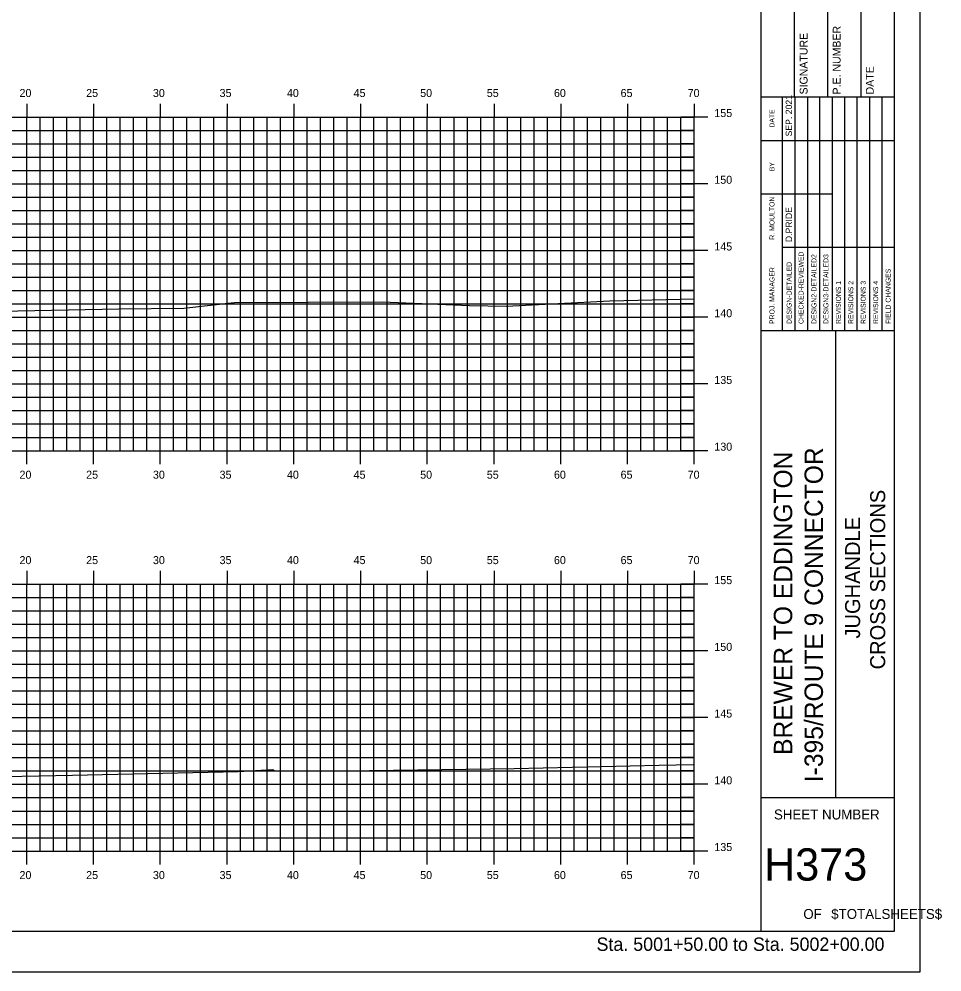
# Model space of a CAD drawing. Extents: x 851195 to 851367, y 365876 to 365986.
# Drawn here: x 851297.6 to 851366.7, y 365875.8 to 365947.2 of the extents above; entities that cross this region are included whole.
import ezdxf

# ---------------------------------------------------------------- set-up
doc = ezdxf.new("R2010")
doc.units = 0
for name, color, linetype in [('BORDER', 7, 'Continuous'), ('H_V ANNOTATION', 7, 'Continuous'), ('MAJOR', 7, 'Continuous'), ('MINOR', 7, 'Continuous'), ('PLOT BOUNDARY', 7, 'Continuous'), ('S_Roadway_Centerline', 7, 'Continuous')]:
    doc.layers.add(name, color=color, linetype=linetype)

msp = doc.modelspace()

# ---------------------------------------------------------------- linework, layer by layer
at = {"layer": 'BORDER'}
for p, q in [((851353.142, 365878.833), (851353.142, 365983.833)), ((851355.642, 365941.336), (851355.642, 365949.984)), ((851358.142, 365941.336), (851358.142, 365949.984)), ((851360.642, 365941.336), (851360.642, 365949.984)), ((851353.142, 365941.336), (851363.142, 365941.336)), ((851353.142, 365923.836), (851363.142, 365923.836)), ((851358.733, 365888.836), (851358.733, 365923.836)), ((851353.142, 365888.836), (851363.142, 365888.836))]:
    msp.add_line(p, q, dxfattribs=at)
msp.add_lwpolyline([(851203.142, 365878.833), (851363.142, 365878.833), (851363.142, 365983.833), (851203.142, 365983.833)], close=True, dxfattribs=at)
for points in [[(851354.757, 365938.086), (851354.757, 365941.336)], [(851355.69, 365923.839), (851355.69, 365941.336)], [(851356.621, 365941.336), (851356.621, 365923.839)], [(851357.553, 365923.839), (851357.553, 365941.336)], [(851358.485, 365923.839), (851358.485, 365941.336)], [(851359.416, 365923.839), (851359.416, 365941.336)], [(851360.348, 365923.839), (851360.348, 365941.336)], [(851361.28, 365923.839), (851361.28, 365941.336)], [(851362.211, 365923.839), (851362.211, 365941.336)], [(851354.758, 365923.839), (851354.758, 365940.63)], [(851353.142, 365938.086), (851363.142, 365938.086)], [(851353.142, 365934.086), (851354.758, 365934.086)], [(851354.757, 365934.086), (851358.484, 365934.086)], [(851354.757, 365930.086), (851363.142, 365930.086)]]:
    msp.add_lwpolyline(points, dxfattribs=at)
at = {"layer": 'MAJOR'}
for p, q in [((851298.142, 365940.835), (851298.142, 365939.833)), ((851303.142, 365940.835), (851303.142, 365939.833)), ((851308.142, 365940.835), (851308.142, 365939.833)), ((851313.142, 365940.835), (851313.142, 365939.833)), ((851318.142, 365940.835), (851318.142, 365939.833)), ((851323.142, 365940.835), (851323.142, 365939.833)), ((851328.142, 365940.835), (851328.142, 365939.833)), ((851333.142, 365940.835), (851333.142, 365939.833)), ((851338.142, 365940.835), (851338.142, 365939.833)), ((851343.142, 365940.835), (851343.142, 365939.833)), ((851348.142, 365940.835), (851348.142, 365939.833)), ((851208.142, 365939.833), (851348.142, 365939.833)), ((851208.142, 365939.833), (851348.142, 365939.833)), ((851298.142, 365914.833), (851298.142, 365939.833)), ((851303.142, 365914.833), (851303.142, 365939.833)), ((851308.142, 365914.833), (851308.142, 365939.833)), ((851313.142, 365914.833), (851313.142, 365939.833)), ((851318.142, 365914.833), (851318.142, 365939.833)), ((851323.142, 365914.833), (851323.142, 365939.833)), ((851328.142, 365914.833), (851328.142, 365939.833)), ((851333.142, 365914.833), (851333.142, 365939.833)), ((851338.142, 365914.833), (851338.142, 365939.833)), ((851343.142, 365914.833), (851343.142, 365939.833)), ((851349.144, 365939.833), (851347.14, 365939.833)), ((851348.142, 365914.833), (851348.142, 365939.833)), ((851348.142, 365914.833), (851348.142, 365939.833)), ((851208.142, 365934.833), (851348.142, 365934.833)), ((851349.144, 365934.833), (851347.14, 365934.833)), ((851208.142, 365929.833), (851348.142, 365929.833)), ((851349.144, 365929.833), (851347.14, 365929.833)), ((851208.142, 365924.833), (851348.142, 365924.833)), ((851349.144, 365924.833), (851347.14, 365924.833)), ((851208.142, 365919.833), (851348.142, 365919.833)), ((851349.144, 365919.833), (851347.14, 365919.833)), ((851208.142, 365914.833), (851348.142, 365914.833)), ((851208.142, 365914.833), (851348.142, 365914.833)), ((851298.142, 365913.831), (851298.142, 365914.833)), ((851303.142, 365913.831), (851303.142, 365914.833)), ((851308.142, 365913.831), (851308.142, 365914.833)), ((851313.142, 365913.831), (851313.142, 365914.833)), ((851318.142, 365913.831), (851318.142, 365914.833)), ((851323.142, 365913.831), (851323.142, 365914.833)), ((851328.142, 365913.831), (851328.142, 365914.833)), ((851333.142, 365913.831), (851333.142, 365914.833)), ((851338.142, 365913.831), (851338.142, 365914.833)), ((851343.142, 365913.831), (851343.142, 365914.833)), ((851349.144, 365914.833), (851347.14, 365914.833)), ((851348.142, 365913.831), (851348.142, 365914.833)), ((851298.142, 365905.835), (851298.142, 365904.833)), ((851303.142, 365905.835), (851303.142, 365904.833)), ((851308.142, 365905.835), (851308.142, 365904.833)), ((851313.142, 365905.835), (851313.142, 365904.833)), ((851318.142, 365905.835), (851318.142, 365904.833)), ((851323.142, 365905.835), (851323.142, 365904.833)), ((851328.142, 365905.835), (851328.142, 365904.833)), ((851333.142, 365905.835), (851333.142, 365904.833)), ((851338.142, 365905.835), (851338.142, 365904.833)), ((851343.142, 365905.835), (851343.142, 365904.833)), ((851348.142, 365905.835), (851348.142, 365904.833)), ((851208.142, 365904.833), (851348.142, 365904.833)), ((851208.142, 365904.833), (851348.142, 365904.833)), ((851298.142, 365884.833), (851298.142, 365904.833)), ((851303.142, 365884.833), (851303.142, 365904.833)), ((851308.142, 365884.833), (851308.142, 365904.833)), ((851313.142, 365884.833), (851313.142, 365904.833)), ((851318.142, 365884.833), (851318.142, 365904.833)), ((851323.142, 365884.833), (851323.142, 365904.833)), ((851328.142, 365884.833), (851328.142, 365904.833)), ((851333.142, 365884.833), (851333.142, 365904.833)), ((851338.142, 365884.833), (851338.142, 365904.833)), ((851343.142, 365884.833), (851343.142, 365904.833)), ((851349.144, 365904.833), (851347.14, 365904.833)), ((851348.142, 365884.833), (851348.142, 365904.833)), ((851348.142, 365884.833), (851348.142, 365904.833)), ((851208.142, 365899.833), (851348.142, 365899.833)), ((851349.144, 365899.833), (851347.14, 365899.833)), ((851208.142, 365894.833), (851348.142, 365894.833)), ((851349.144, 365894.833), (851347.14, 365894.833)), ((851208.142, 365889.833), (851348.142, 365889.833)), ((851349.144, 365889.833), (851347.14, 365889.833)), ((851208.142, 365884.833), (851348.142, 365884.833)), ((851208.142, 365884.833), (851348.142, 365884.833)), ((851298.142, 365883.831), (851298.142, 365884.833)), ((851303.142, 365883.831), (851303.142, 365884.833)), ((851308.142, 365883.831), (851308.142, 365884.833)), ((851313.142, 365883.831), (851313.142, 365884.833)), ((851318.142, 365883.831), (851318.142, 365884.833)), ((851323.142, 365883.831), (851323.142, 365884.833)), ((851328.142, 365883.831), (851328.142, 365884.833)), ((851333.142, 365883.831), (851333.142, 365884.833)), ((851338.142, 365883.831), (851338.142, 365884.833)), ((851343.142, 365883.831), (851343.142, 365884.833)), ((851349.144, 365884.833), (851347.14, 365884.833)), ((851348.142, 365883.831), (851348.142, 365884.833))]:
    msp.add_line(p, q, dxfattribs=at)
at = {"layer": 'MINOR'}
for p, q in [((851299.142, 365914.833), (851299.142, 365939.833)), ((851300.142, 365914.833), (851300.142, 365939.833)), ((851301.142, 365914.833), (851301.142, 365939.833)), ((851302.142, 365914.833), (851302.142, 365939.833)), ((851304.142, 365914.833), (851304.142, 365939.833)), ((851305.142, 365914.833), (851305.142, 365939.833)), ((851306.142, 365914.833), (851306.142, 365939.833)), ((851307.142, 365914.833), (851307.142, 365939.833)), ((851309.142, 365914.833), (851309.142, 365939.833)), ((851310.142, 365914.833), (851310.142, 365939.833)), ((851311.142, 365914.833), (851311.142, 365939.833)), ((851312.142, 365914.833), (851312.142, 365939.833)), ((851314.142, 365914.833), (851314.142, 365939.833)), ((851315.142, 365914.833), (851315.142, 365939.833)), ((851316.142, 365914.833), (851316.142, 365939.833)), ((851317.142, 365914.833), (851317.142, 365939.833)), ((851319.142, 365914.833), (851319.142, 365939.833)), ((851320.142, 365914.833), (851320.142, 365939.833)), ((851321.142, 365914.833), (851321.142, 365939.833)), ((851322.142, 365914.833), (851322.142, 365939.833)), ((851324.142, 365914.833), (851324.142, 365939.833)), ((851325.142, 365914.833), (851325.142, 365939.833)), ((851326.142, 365914.833), (851326.142, 365939.833)), ((851327.142, 365914.833), (851327.142, 365939.833)), ((851329.142, 365914.833), (851329.142, 365939.833)), ((851330.142, 365914.833), (851330.142, 365939.833)), ((851331.142, 365914.833), (851331.142, 365939.833)), ((851332.142, 365914.833), (851332.142, 365939.833)), ((851334.142, 365914.833), (851334.142, 365939.833)), ((851335.142, 365914.833), (851335.142, 365939.833)), ((851336.142, 365914.833), (851336.142, 365939.833)), ((851337.142, 365914.833), (851337.142, 365939.833)), ((851339.142, 365914.833), (851339.142, 365939.833)), ((851340.142, 365914.833), (851340.142, 365939.833)), ((851341.142, 365914.833), (851341.142, 365939.833)), ((851342.142, 365914.833), (851342.142, 365939.833)), ((851344.142, 365914.833), (851344.142, 365939.833)), ((851345.142, 365914.833), (851345.142, 365939.833)), ((851346.142, 365914.833), (851346.142, 365939.833)), ((851347.142, 365914.833), (851347.142, 365939.833)), ((851208.142, 365938.833), (851348.142, 365938.833)), ((851348.142, 365938.833), (851347.14, 365938.833)), ((851208.142, 365937.833), (851348.142, 365937.833)), ((851348.142, 365937.833), (851347.14, 365937.833)), ((851208.142, 365936.833), (851348.142, 365936.833)), ((851348.142, 365936.833), (851347.14, 365936.833)), ((851208.142, 365935.833), (851348.142, 365935.833)), ((851348.142, 365935.833), (851347.14, 365935.833)), ((851208.142, 365933.833), (851348.142, 365933.833)), ((851348.142, 365933.833), (851347.14, 365933.833)), ((851208.142, 365932.833), (851348.142, 365932.833)), ((851348.142, 365932.833), (851347.14, 365932.833)), ((851208.142, 365931.833), (851348.142, 365931.833)), ((851348.142, 365931.833), (851347.14, 365931.833)), ((851208.142, 365930.833), (851348.142, 365930.833)), ((851348.142, 365930.833), (851347.14, 365930.833)), ((851208.142, 365928.833), (851348.142, 365928.833)), ((851348.142, 365928.833), (851347.14, 365928.833)), ((851208.142, 365927.833), (851348.142, 365927.833)), ((851348.142, 365927.833), (851347.14, 365927.833)), ((851208.142, 365926.833), (851348.142, 365926.833)), ((851348.142, 365926.833), (851347.14, 365926.833)), ((851208.142, 365925.833), (851348.142, 365925.833)), ((851348.142, 365925.833), (851347.14, 365925.833)), ((851208.142, 365923.833), (851348.142, 365923.833)), ((851348.142, 365923.833), (851347.14, 365923.833)), ((851208.142, 365922.833), (851348.142, 365922.833)), ((851348.142, 365922.833), (851347.14, 365922.833)), ((851208.142, 365921.833), (851348.142, 365921.833)), ((851348.142, 365921.833), (851347.14, 365921.833)), ((851208.142, 365920.833), (851348.142, 365920.833)), ((851348.142, 365920.833), (851347.14, 365920.833)), ((851208.142, 365918.833), (851348.142, 365918.833)), ((851348.142, 365918.833), (851347.14, 365918.833)), ((851208.142, 365917.833), (851348.142, 365917.833)), ((851348.142, 365917.833), (851347.14, 365917.833)), ((851208.142, 365916.833), (851348.142, 365916.833)), ((851348.142, 365916.833), (851347.14, 365916.833)), ((851208.142, 365915.833), (851348.142, 365915.833)), ((851348.142, 365915.833), (851347.14, 365915.833)), ((851299.142, 365884.833), (851299.142, 365904.833)), ((851300.142, 365884.833), (851300.142, 365904.833)), ((851301.142, 365884.833), (851301.142, 365904.833)), ((851302.142, 365884.833), (851302.142, 365904.833)), ((851304.142, 365884.833), (851304.142, 365904.833)), ((851305.142, 365884.833), (851305.142, 365904.833)), ((851306.142, 365884.833), (851306.142, 365904.833)), ((851307.142, 365884.833), (851307.142, 365904.833)), ((851309.142, 365884.833), (851309.142, 365904.833)), ((851310.142, 365884.833), (851310.142, 365904.833)), ((851311.142, 365884.833), (851311.142, 365904.833)), ((851312.142, 365884.833), (851312.142, 365904.833)), ((851314.142, 365884.833), (851314.142, 365904.833)), ((851315.142, 365884.833), (851315.142, 365904.833)), ((851316.142, 365884.833), (851316.142, 365904.833)), ((851317.142, 365884.833), (851317.142, 365904.833)), ((851319.142, 365884.833), (851319.142, 365904.833)), ((851320.142, 365884.833), (851320.142, 365904.833)), ((851321.142, 365884.833), (851321.142, 365904.833)), ((851322.142, 365884.833), (851322.142, 365904.833)), ((851324.142, 365884.833), (851324.142, 365904.833)), ((851325.142, 365884.833), (851325.142, 365904.833)), ((851326.142, 365884.833), (851326.142, 365904.833)), ((851327.142, 365884.833), (851327.142, 365904.833)), ((851329.142, 365884.833), (851329.142, 365904.833)), ((851330.142, 365884.833), (851330.142, 365904.833)), ((851331.142, 365884.833), (851331.142, 365904.833)), ((851332.142, 365884.833), (851332.142, 365904.833)), ((851334.142, 365884.833), (851334.142, 365904.833)), ((851335.142, 365884.833), (851335.142, 365904.833)), ((851336.142, 365884.833), (851336.142, 365904.833)), ((851337.142, 365884.833), (851337.142, 365904.833)), ((851339.142, 365884.833), (851339.142, 365904.833)), ((851340.142, 365884.833), (851340.142, 365904.833)), ((851341.142, 365884.833), (851341.142, 365904.833)), ((851342.142, 365884.833), (851342.142, 365904.833)), ((851344.142, 365884.833), (851344.142, 365904.833)), ((851345.142, 365884.833), (851345.142, 365904.833)), ((851346.142, 365884.833), (851346.142, 365904.833)), ((851347.142, 365884.833), (851347.142, 365904.833)), ((851208.142, 365903.833), (851348.142, 365903.833)), ((851348.142, 365903.833), (851347.14, 365903.833)), ((851208.142, 365902.833), (851348.142, 365902.833)), ((851348.142, 365902.833), (851347.14, 365902.833)), ((851208.142, 365901.833), (851348.142, 365901.833)), ((851348.142, 365901.833), (851347.14, 365901.833)), ((851208.142, 365900.833), (851348.142, 365900.833)), ((851348.142, 365900.833), (851347.14, 365900.833)), ((851208.142, 365898.833), (851348.142, 365898.833)), ((851348.142, 365898.833), (851347.14, 365898.833)), ((851208.142, 365897.833), (851348.142, 365897.833)), ((851348.142, 365897.833), (851347.14, 365897.833)), ((851208.142, 365896.833), (851348.142, 365896.833)), ((851348.142, 365896.833), (851347.14, 365896.833)), ((851208.142, 365895.833), (851348.142, 365895.833)), ((851348.142, 365895.833), (851347.14, 365895.833)), ((851208.142, 365893.833), (851348.142, 365893.833)), ((851348.142, 365893.833), (851347.14, 365893.833)), ((851208.142, 365892.833), (851348.142, 365892.833)), ((851348.142, 365892.833), (851347.14, 365892.833)), ((851208.142, 365891.833), (851348.142, 365891.833)), ((851348.142, 365891.833), (851347.14, 365891.833)), ((851208.142, 365890.833), (851348.142, 365890.833)), ((851348.142, 365890.833), (851347.14, 365890.833)), ((851208.142, 365888.833), (851348.142, 365888.833)), ((851348.142, 365888.833), (851347.14, 365888.833)), ((851208.142, 365887.833), (851348.142, 365887.833)), ((851348.142, 365887.833), (851347.14, 365887.833)), ((851208.142, 365886.833), (851348.142, 365886.833)), ((851348.142, 365886.833), (851347.14, 365886.833)), ((851208.142, 365885.833), (851348.142, 365885.833)), ((851348.142, 365885.833), (851347.14, 365885.833))]:
    msp.add_line(p, q, dxfattribs=at)
at = {"layer": 'PLOT BOUNDARY'}
msp.add_lwpolyline([(851195.049, 365875.774), (851365.049, 365875.774), (851365.049, 365985.774), (851195.049, 365985.774)], close=True, dxfattribs=at)
at = {"layer": 'S_Roadway_Centerline'}
for points in [[(851296.222, 365925.276), (851305.027, 365925.458), (851309.904, 365925.514), (851313.671, 365925.94), (851324.759, 365925.988), (851331.302, 365925.709), (851334.072, 365925.654), (851341.804, 365926.069), (851348.142, 365926.208)], [(851296.52, 365890.412), (851301.569, 365890.522), (851313.974, 365890.799), (851316.583, 365890.933), (851316.695, 365890.853), (851320.183, 365890.818), (851334.654, 365891.025), (851345.501, 365891.264), (851348.063, 365891.312), (851348.142, 365891.321)]]:
    msp.add_lwpolyline(points, dxfattribs=at)

# ---------------------------------------------------------------- texts
at = {"layer": 'BORDER'}
for s, height, p in [('SIGNATURE', 0.5906, (851356.623, 365941.528)), ('P.E. NUMBER', 0.59055, (851359.103, 365941.528)), ('DATE', 0.5906, (851361.583, 365941.528)), ('SEP. 2021', 0.4845, (851355.465, 365938.382)), ('DATE', 0.3714, (851354.146, 365939.042)), ('BY', 0.3714, (851354.146, 365935.771)), ('R. MOULTON', 0.3727, (851354.146, 365930.639)), ('D.PRIDE', 0.4845, (851355.465, 365930.459)), ('CHECKED-REVIEWED', 0.37275, (851356.323, 365924.324)), ('DESIGN2-DETAILED2', 0.37275, (851357.292, 365924.324)), ('DESIGN3-DETAILED3', 0.37275, (851358.186, 365924.324)), ('PROJ. MANAGER', 0.37275, (851354.146, 365924.324)), ('DESIGN-DETAILED', 0.37275, (851355.429, 365924.324)), ('FIELD CHANGES', 0.37275, (851362.845, 365924.324)), ('REVISIONS 1', 0.37275, (851359.118, 365924.324)), ('REVISIONS 2', 0.37275, (851360.05, 365924.324)), ('REVISIONS 3', 0.37275, (851360.981, 365924.324)), ('REVISIONS 4', 0.37275, (851361.913, 365924.324)), ('I-395/ROUTE 9 CONNECTOR', 1.37787, (851357.777, 365889.998)), ('BREWER TO EDDINGTON', 1.37787, (851355.476, 365892.038)), ('CROSS SECTIONS', 1.125, (851362.439, 365898.444)), ('JUGHANDLE', 1.125, (851360.561, 365900.756))]:
    msp.add_text(s, height=height, rotation=90, dxfattribs=at).set_placement(p)
for s, height, p in [('SHEET NUMBER', 0.74527, (851354.108, 365887.2)), ('H373', 2.4194, (851353.362, 365882.616)), ('OF', 0.7453, (851356.309, 365879.746)), ('$TOTALSHEETS$', 0.74527, (851358.399, 365879.746))]:
    msp.add_text(s, height=height, dxfattribs=at).set_placement(p)
at = {"layer": 'H_V ANNOTATION'}
for s, height, p in [('20', 0.6, (851297.596, 365941.333)), ('25', 0.6, (851302.588, 365941.333)), ('30', 0.6, (851307.591, 365941.333)), ('35', 0.6, (851312.583, 365941.333)), ('40', 0.6, (851317.628, 365941.333)), ('45', 0.6, (851322.62, 365941.333)), ('50', 0.6, (851327.607, 365941.333)), ('55', 0.6, (851332.599, 365941.333)), ('60', 0.6, (851337.628, 365941.333)), ('65', 0.6, (851342.62, 365941.333)), ('70', 0.6, (851347.644, 365941.333)), ('155', 0.6, (851349.642, 365939.833)), ('150', 0.6, (851349.642, 365934.833)), ('145', 0.6, (851349.642, 365929.833)), ('140', 0.6, (851349.642, 365924.833)), ('135', 0.6, (851349.642, 365919.833)), ('130', 0.6, (851349.642, 365914.833)), ('20', 0.6, (851297.596, 365912.733)), ('25', 0.6, (851302.588, 365912.733)), ('30', 0.6, (851307.591, 365912.733)), ('35', 0.6, (851312.583, 365912.733)), ('40', 0.6, (851317.628, 365912.733)), ('45', 0.6, (851322.62, 365912.733)), ('50', 0.6, (851327.607, 365912.733)), ('55', 0.6, (851332.599, 365912.733)), ('60', 0.6, (851337.628, 365912.733)), ('65', 0.6, (851342.62, 365912.733)), ('70', 0.6, (851347.644, 365912.733)), ('20', 0.6, (851297.596, 365906.333)), ('25', 0.6, (851302.588, 365906.333)), ('30', 0.6, (851307.591, 365906.333)), ('35', 0.6, (851312.583, 365906.333)), ('40', 0.6, (851317.628, 365906.333)), ('45', 0.6, (851322.62, 365906.333)), ('50', 0.6, (851327.607, 365906.333)), ('55', 0.6, (851332.599, 365906.333)), ('60', 0.6, (851337.628, 365906.333)), ('65', 0.6, (851342.62, 365906.333)), ('70', 0.6, (851347.644, 365906.333)), ('155', 0.6, (851349.642, 365904.833)), ('150', 0.6, (851349.642, 365899.833)), ('145', 0.6, (851349.642, 365894.833)), ('140', 0.6, (851349.642, 365889.833)), ('135', 0.6, (851349.642, 365884.833)), ('20', 0.6, (851297.596, 365882.733)), ('25', 0.6, (851302.588, 365882.733)), ('30', 0.6, (851307.591, 365882.733)), ('35', 0.6, (851312.583, 365882.733)), ('40', 0.6, (851317.628, 365882.733)), ('45', 0.6, (851322.62, 365882.733)), ('50', 0.6, (851327.607, 365882.733)), ('55', 0.6, (851332.599, 365882.733)), ('60', 0.6, (851337.628, 365882.733)), ('65', 0.6, (851342.62, 365882.733)), ('70', 0.6, (851347.644, 365882.733)), ('Sta. 5001+50.00 to Sta. 5002+00.00', 1.0002, (851340.818, 365877.353))]:
    msp.add_text(s, height=height, dxfattribs=at).set_placement(p)

doc.saveas('drawing.dxf')
